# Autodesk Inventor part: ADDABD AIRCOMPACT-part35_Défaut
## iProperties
Shininess: 64.0
Length Units: 11269
Angle Units: 11279
Time Units: 11290
Mass Units: 11283
Length Display Precision: 3
Angle Display Precision: 2
Compacted: True
Part Number: ADDABD AIRCOMPACT-part35_Défaut
Document SubType Name: Modeling
Created: 2006-01
Material: Par défaut
Designer: riri
Density: 0.0
Volumn: 0.0
Area: 0.0
PropertySet Name: Model Information
Control State: 0
Master: False
Checked Out: False
Author: riri
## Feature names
1. Base1
